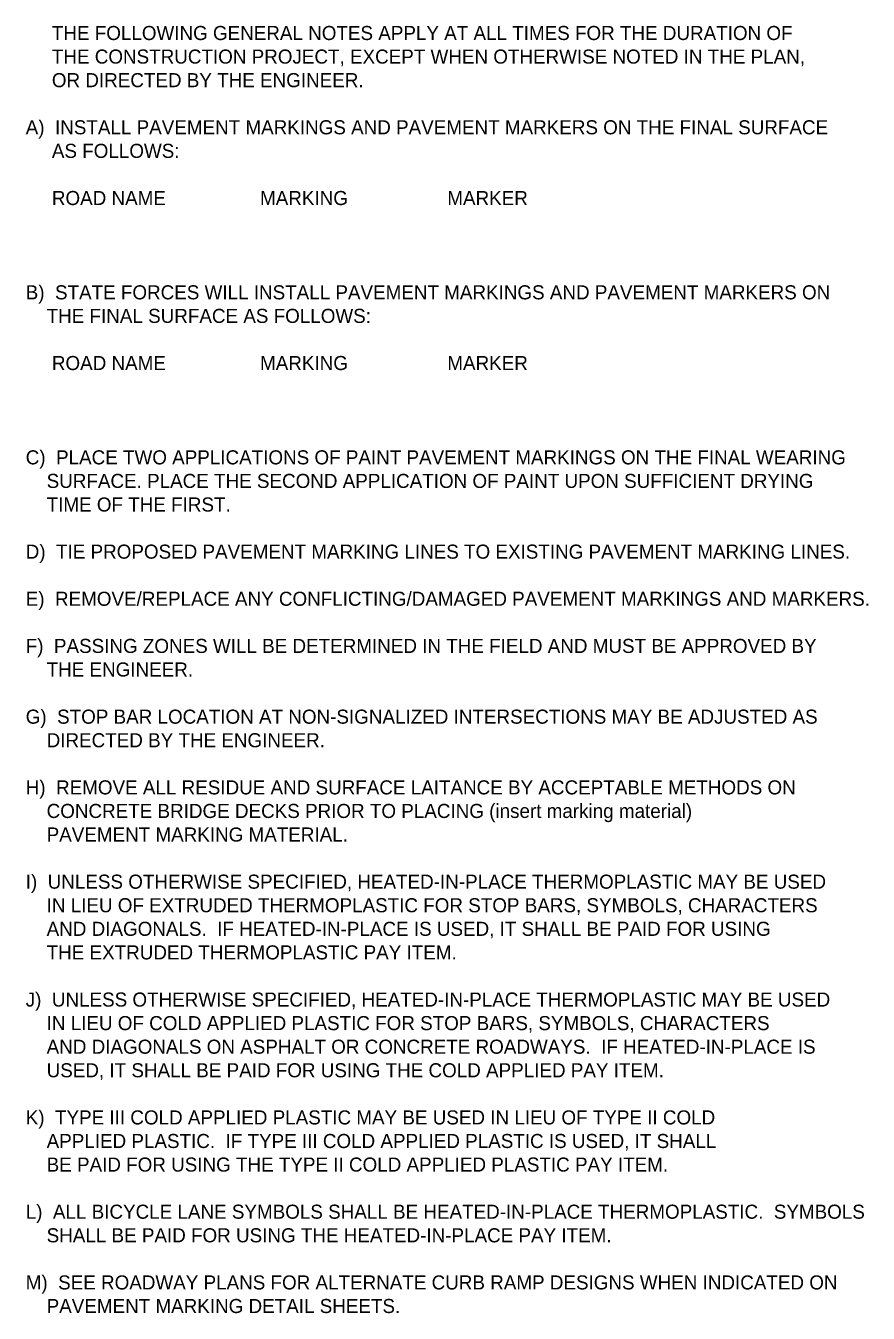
# Model space of a CAD drawing. Extents: x 2088685 to 2091711, y 751320 to 752417.
# Drawn here: x 2088685 to 2089085, y 751438 to 752048 of the extents above; entities that cross this region are included whole.
import ezdxf

# ---------------------------------------------------------------- set-up
doc = ezdxf.new("R2010")
doc.units = 0
doc.layers.add('Default', color=7, linetype='Continuous')

msp = doc.modelspace()

# ---------------------------------------------------------------- texts
at = {"layer": 'Default'}
for s, p in [('            THE FOLLOWING GENERAL NOTES APPLY AT ALL TIMES FOR THE DURATION OF', (2088668.13, 752041.37)), ('            THE CONSTRUCTION PROJECT, EXCEPT WHEN OTHERWISE NOTED IN THE PLAN,', (2088668.13, 752030.2)), ('            OR DIRECTED BY THE ENGINEER.', (2088668.13, 752019.03)), ('       A)  INSTALL PAVEMENT MARKINGS AND PAVEMENT MARKERS ON THE FINAL SURFACE', (2088668.13, 751996.69)), ('            AS FOLLOWS:', (2088668.13, 751985.52)), ('            ROAD NAME                  MARKING                   MARKER            ', (2088668.13, 751963.17)), ('       B)  STATE FORCES WILL INSTALL PAVEMENT MARKINGS AND PAVEMENT MARKERS ON', (2088668.13, 751918.49)), ('           THE FINAL SURFACE AS FOLLOWS:', (2088668.13, 751907.32)), ('            ROAD NAME                  MARKING                   MARKER           ', (2088668.13, 751884.98)), ('       C)  PLACE TWO APPLICATIONS OF PAINT PAVEMENT MARKINGS ON THE FINAL WEARING', (2088668.13, 751840.29)), ('           SURFACE. PLACE THE SECOND APPLICATION OF PAINT UPON SUFFICIENT DRYING', (2088668.13, 751829.12)), ('           TIME OF THE FIRST.', (2088668.13, 751817.95)), ('       D)  TIE PROPOSED PAVEMENT MARKING LINES TO EXISTING PAVEMENT MARKING LINES.', (2088668.13, 751795.61)), ('       E)  REMOVE/REPLACE ANY CONFLICTING/DAMAGED PAVEMENT MARKINGS AND MARKERS.', (2088668.13, 751773.27)), ('       F)  PASSING ZONES WILL BE DETERMINED IN THE FIELD AND MUST BE APPROVED BY', (2088668.13, 751750.93)), ('           THE ENGINEER.', (2088668.13, 751739.76)), ('       G)  STOP BAR LOCATION AT NON-SIGNALIZED INTERSECTIONS MAY BE ADJUSTED AS ', (2088668.13, 751717.41)), ('           DIRECTED BY THE ENGINEER.', (2088668.13, 751706.24)), ('       H)  REMOVE ALL RESIDUE AND SURFACE LAITANCE BY ACCEPTABLE METHODS ON ', (2088668.13, 751683.9)), ('           CONCRETE BRIDGE DECKS PRIOR TO PLACING (insert marking material)  ', (2088668.13, 751672.73)), ('           PAVEMENT MARKING MATERIAL.', (2088668.13, 751661.56)), ('       I)  UNLESS OTHERWISE SPECIFIED, HEATED-IN-PLACE THERMOPLASTIC MAY BE USED', (2088668.13, 751639.22)), ('           IN LIEU OF EXTRUDED THERMOPLASTIC FOR STOP BARS, SYMBOLS, CHARACTERS ', (2088668.13, 751628.05)), ('           AND DIAGONALS.  IF HEATED-IN-PLACE IS USED, IT SHALL BE PAID FOR USING ', (2088668.13, 751616.88)), ('           THE EXTRUDED THERMOPLASTIC PAY ITEM.', (2088668.13, 751605.71)), ('       J)  UNLESS OTHERWISE SPECIFIED, HEATED-IN-PLACE THERMOPLASTIC MAY BE USED', (2088668.13, 751583.36)), ('           IN LIEU OF COLD APPLIED PLASTIC FOR STOP BARS, SYMBOLS, CHARACTERS ', (2088668.13, 751572.19)), ('           AND DIAGONALS ON ASPHALT OR CONCRETE ROADWAYS.  IF HEATED-IN-PLACE IS', (2088668.13, 751561.02)), ('           USED, IT SHALL BE PAID FOR USING THE COLD APPLIED PAY ITEM.', (2088668.13, 751549.85)), ('       K)  TYPE III COLD APPLIED PLASTIC MAY BE USED IN LIEU OF TYPE II COLD ', (2088668.13, 751527.51)), ('           APPLIED PLASTIC.  IF TYPE III COLD APPLIED PLASTIC IS USED, IT SHALL', (2088668.13, 751516.34)), ('           BE PAID FOR USING THE TYPE II COLD APPLIED PLASTIC PAY ITEM.', (2088668.13, 751505.17)), ('       L)  ALL BICYCLE LANE SYMBOLS SHALL BE HEATED-IN-PLACE THERMOPLASTIC.  SYMBOLS', (2088668.13, 751482.83)), ('           SHALL BE PAID FOR USING THE HEATED-IN-PLACE PAY ITEM.', (2088668.13, 751471.65)), ('       M)  SEE ROADWAY PLANS FOR ALTERNATE CURB RAMP DESIGNS WHEN INDICATED ON ', (2088668.13, 751449.31)), ('           PAVEMENT MARKING DETAIL SHEETS.', (2088668.13, 751438.14))]:
    msp.add_text(s, height=6.6709, rotation=360, dxfattribs=at).set_placement(p)

doc.saveas('drawing.dxf')
